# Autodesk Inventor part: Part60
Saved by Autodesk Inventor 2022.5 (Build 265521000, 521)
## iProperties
Created: 2024-12
Part Number: Part60
Material: Generic
Document SubType Name: Modeling
Designer: AdminForWorker
Density: 1 g/cm^3
Appearance: Default
Author: AdminForWorker
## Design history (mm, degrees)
feature "Body1"
feature "Body2"
body "Solid1"
body "Solid2"
